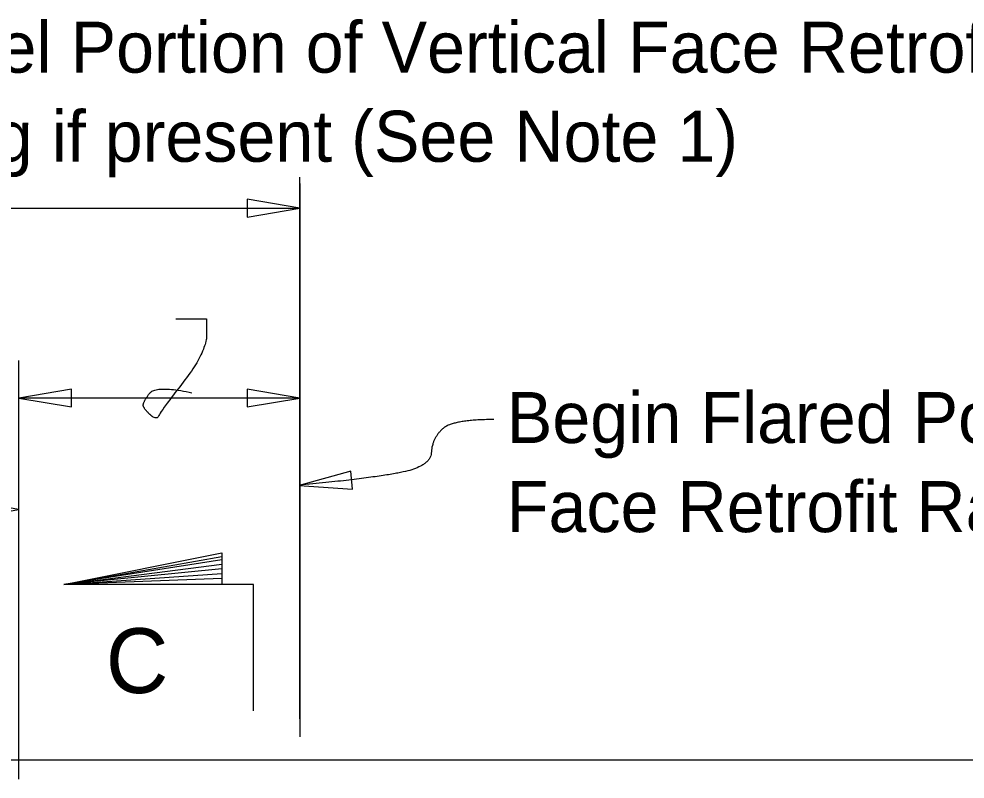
# Model space of a CAD drawing. Extents: x 1.5 to 68.7, y 0 to 31.1.
# Drawn here: x 6.295 to 10.034, y 13.743 to 16.745 of the extents above; entities that cross this region are included whole.
import ezdxf

# ---------------------------------------------------------------- set-up
doc = ezdxf.new("R2010")
doc.units = 0
for name, color, linetype in [('Dimension', 7, 'Continuous'), ('TextStructures', 7, 'Continuous'), ('TrafBarrierConc', 7, 'Continuous')]:
    doc.layers.add(name, color=color, linetype=linetype)

msp = doc.modelspace()

# ---------------------------------------------------------------- linework, layer by layer
at = {"layer": 'Dimension'}
for p, q in [((7.4053, 13.981), (7.4053, 16.1198)), ((7.4052, 16.0948), (7.4052, 13.9093)), ((6.2955, 13.7426), (6.2955, 15.3961)), ((7.4053, 15.2478), (6.2955, 15.2478)), ((6.4727, 14.5119), (7.0977, 14.6219)), ((7.0977, 14.6085), (6.4727, 14.5119)), ((6.4727, 14.5119), (7.0977, 14.5919)), ((7.0977, 14.5735), (6.4727, 14.5119)), ((6.4727, 14.5119), (7.0977, 14.5552)), ((7.0977, 14.5352), (6.4727, 14.5119))]:
    msp.add_line(p, q, dxfattribs=at)
for points in [[(7.4053, 15.9978), (7.197, 16.0331), (7.197, 15.9626)], [(6.2955, 15.2478), (6.5037, 15.2126), (6.5037, 15.2831)], [(7.4053, 15.2478), (7.197, 15.2831), (7.197, 15.2126)], [(7.4031, 14.903), (7.6138, 14.8883), (7.6069, 14.9585)], [(6.2955, 14.8073), (6.0872, 14.8426), (6.0872, 14.772)]]:
    msp.add_lwpolyline(points, close=True, dxfattribs=at)
for points in [[(3.8717, 15.9978), (7.4052, 15.9978)], [(7.2227, 14.0119), (7.2227, 14.5119), (6.4727, 14.5119), (7.0977, 14.6369), (7.0977, 14.5119)]]:
    msp.add_lwpolyline(points, dxfattribs=at)
for points in [[(6.9159, 15.5612), (7.0366, 15.5612), (7.0366, 15.5612), (7.0366, 15.4286), (6.8564, 15.1975), (6.8394, 15.1584), (6.7867, 15.2077), (6.7867, 15.2315), (6.8343, 15.2995), (6.9788, 15.2689)], [(8.1719, 15.1629), (8.0057, 15.1629), (7.9277, 15.0849), (7.9225, 14.9809), (7.7199, 14.9341), (7.403, 14.903)]]:
    msp.add_open_spline(points, degree=2, dxfattribs=at)
at = {"layer": 'TrafBarrierConc'}
msp.add_line((14.1461, 13.8178), (3.8717, 13.8178), dxfattribs=at)

# ---------------------------------------------------------------- texts
at = {"layer": 'Dimension'}
for s, p in [('Parallel Portion of Vertical Face Retrofit ', (5.5257, 16.5332)), ('Railing if present (See Note 1)', (5.5257, 16.1812)), ('Begin Flared Portion of Vertical ', (8.2235, 15.0701)), ('Face Retrofit Railing', (8.2235, 14.7181))]:
    msp.add_text(s, height=0.2016, dxfattribs=at).set_placement(p)
at = {"layer": 'TextStructures'}
msp.add_text('C', height=0.256, dxfattribs=at).set_placement((6.6388, 14.0824))

doc.saveas('drawing.dxf')
